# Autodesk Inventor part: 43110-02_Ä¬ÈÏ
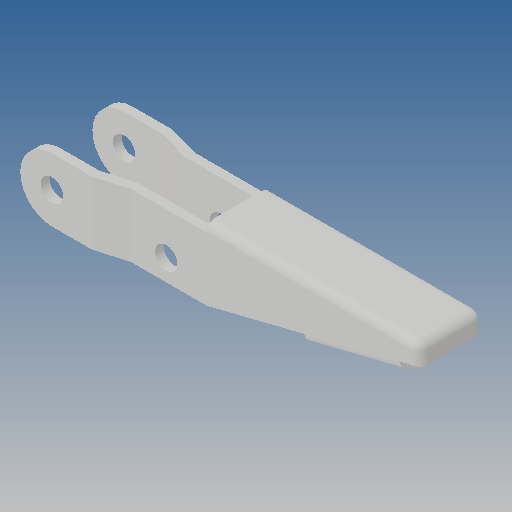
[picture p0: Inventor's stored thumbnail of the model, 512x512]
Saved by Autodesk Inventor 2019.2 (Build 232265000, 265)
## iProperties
Created: 2010-06
Part Number: 43110-02_Ä¬ÈÏ
Material: Ogólny
Document SubType Name: Modeling
Designer: CADENGINEERING4
Density: 1 g/cm^3
Appearance: Domyślna
Author: CADENGINEERING4
Revision Number: ÈÎºÎ
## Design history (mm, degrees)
feature "NONE"
node "Bryła1"
